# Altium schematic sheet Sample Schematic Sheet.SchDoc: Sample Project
size Letter; ApprovedBy: Jeremy Blum; CheckedBy: Jeremy Blum; Author: Jeremy Blum; CompanyName: Blum Idea Labs, LLC.; DrawnBy: Jeremy Blum; Engineer: Jeremy Blum; Organization: Blum Idea Labs, LLC.; Address1: P. Sherman; Address2: 42 Wallaby Way; Address3: Sydney, NSW; Address4: Australia; DocumentNumber: 1; Revision: A; SheetNumber: 1; SheetTotal: 1
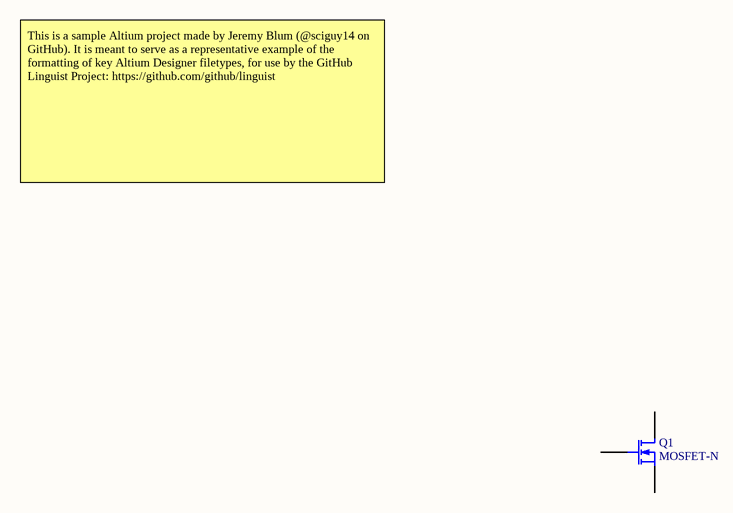
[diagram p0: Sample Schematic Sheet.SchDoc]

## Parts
Q1  MOSFET-N  [E3]

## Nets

Not connected (* = marked no-connect by the designer): Q1 1(D) 2(G) 3(S)

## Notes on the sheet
- This is a sample Altium project made by Jeremy Blum (@sciguy14 on GitHub). It is meant to serve as a representative example of the formatting of key Altium Designer filetypes, for use by the GitHub Linguist Project: https://github.com/github/linguist

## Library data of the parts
Q1 = MOSFET-N: N-Channel MOSFET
